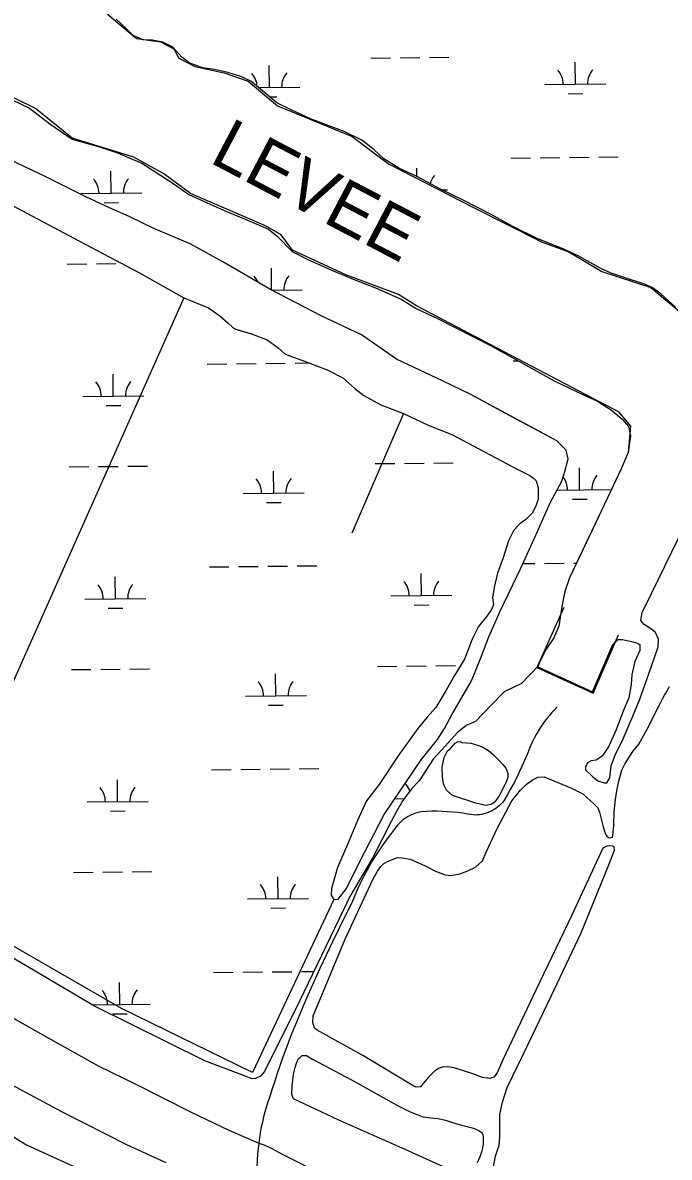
# Model space of a CAD drawing. Extents: x 3734862 to 3772949, y 391520 to 417239.
# Drawn here: x 3766777 to 3767838, y 398891 to 400752 of the extents above; entities that cross this region are included whole.
import ezdxf

# ---------------------------------------------------------------- set-up
doc = ezdxf.new("R2010")
doc.units = 0
for name, color, linetype in [('V-LEVE-TOET', 7, 'Continuous'), ('V-RIVR-IDEN', 7, 'Continuous'), ('V-ROAD-CNTR', 7, 'Continuous'), ('V-RRAP-FSHR', 7, 'Continuous'), ('V-TOPO-SHOR', 7, 'Continuous'), ('V-WETL-SWMP', 7, 'Continuous')]:
    doc.layers.add(name, color=color, linetype=linetype)

msp = doc.modelspace()

# ---------------------------------------------------------------- linework, layer by layer
at = {"layer": 'V-LEVE-TOET'}
for points in [[(3766000.7, 399623.6), (3766051.8, 399583.7), (3766152.7, 399513.4), (3766206.1, 399474.7), (3766298, 399402.4), (3766368.4, 399353.5), (3766423.4, 399316.3), (3766476.1, 399284.7), (3766539.4, 399247.6), (3766612.2, 399205), (3766714.3, 399145.7), (3766810.5, 399092), (3766901.1, 399040.7), (3766963.2, 399010.7), (3767052.6, 398965.3), (3767115.9, 398935.3), (3767147.6, 398921.9), (3767164.7, 398914.1), (3767174.6, 398910.9), (3767185.3, 398905.8), (3767205.5, 398894.7), (3767269.2, 398862.4)], [(3765933.4, 399554.7), (3765986.5, 399511.2), (3766080.7, 399441.7), (3766204.5, 399354.8), (3766290, 399298.3), (3766366.4, 399244.6), (3766432.5, 399199.2), (3766491.1, 399164.4), (3766570.6, 399118.6), (3766618.1, 399090.6), (3766684.6, 399052.3), (3766758.6, 399010.5), (3766842.5, 398965.4), (3766947.7, 398911.8), (3767012.6, 398882.2)]]:
    msp.add_lwpolyline(points, dxfattribs=at)
at = {"layer": 'V-ROAD-CNTR'}
for points in [[(3765561.3, 399764.9), (3765755.5, 399602.6), (3766144.5, 399300.8), (3766783.9, 398911.4), (3767702.3, 398491.7), (3768862.8, 397971.9), (3769048, 397895.2), (3769757.8, 397573.5), (3770042.5, 397441.9), (3770082, 397419.9), (3770108.8, 397401), (3770359.7, 397267.3)], [(3767654.6, 399629.5), (3767650.1, 399625), (3767645.7, 399620.4), (3767641.5, 399615.6), (3767637.5, 399610.7), (3767633.6, 399605.6), (3767629.9, 399600.4), (3767626.3, 399595.1), (3767623, 399589.7), (3767619.8, 399584.2), (3767616.8, 399578.6), (3767614, 399572.9), (3767611.3, 399567.1), (3767608.9, 399561.2), (3767605, 399551.3), (3767600.8, 399541.6), (3767596.5, 399531.9), (3767592, 399522.3), (3767587.4, 399512.8), (3767582.5, 399503.3), (3767577.4, 399494), (3767572.2, 399484.8), (3767566.8, 399475.6), (3767564.5, 399472.8), (3767562.1, 399470.2), (3767559.5, 399467.7), (3767556.7, 399465.4), (3767553.8, 399463.2), (3767550.8, 399461.2), (3767547.7, 399459.4), (3767544.4, 399457.8), (3767541.1, 399456.4), (3767537.7, 399455.2), (3767534.2, 399454.2), (3767530.7, 399453.4), (3767527.2, 399452.8), (3767523.6, 399452.5), (3767520, 399452.3), (3767516.3, 399452.4), (3767507.9, 399453.9), (3767499.5, 399455.2), (3767491, 399456.3), (3767482.6, 399457.1), (3767474, 399457.7), (3767465.5, 399458.2), (3767457, 399458.4), (3767448.5, 399458.4), (3767439.9, 399458.1), (3767431.4, 399457.7), (3767427.7, 399456.9), (3767424.1, 399455.9), (3767420.5, 399454.7), (3767416.9, 399453.3), (3767413.5, 399451.8), (3767410.1, 399450), (3767406.9, 399448.1), (3767403.8, 399445.9), (3767400.8, 399443.6), (3767397.9, 399441.2), (3767395.1, 399438.6), (3767392.5, 399435.8), (3767390.1, 399432.9), (3767387.8, 399429.9), (3767385.7, 399426.8), (3767379.7, 399419), (3767373.9, 399411.2), (3767368.2, 399403.2), (3767362.7, 399395.1), (3767357.4, 399386.9), (3767352.2, 399378.6), (3767347.2, 399370.2), (3767342.5, 399361.6), (3767337.8, 399353), (3767333.4, 399344.3), (3767329.1, 399335.5), (3767325.1, 399326.6), (3767321.2, 399317.6), (3767317.5, 399308.5), (3767306.7, 399287.1), (3767296, 399265.6), (3767285.5, 399244), (3767275.2, 399222.3), (3767265.1, 399200.6), (3767255.1, 399178.7), (3767245.4, 399156.8), (3767235.9, 399134.8), (3767226.5, 399112.6), (3767217.4, 399090.5), (3767212.8, 399078.1), (3767208.3, 399065.7), (3767203.8, 399053.2), (3767199.4, 399040.8), (3767195.1, 399028.3), (3767190.9, 399015.8)], [(3767190.9, 399015.8), (3767186.7, 399003.3), (3767182.7, 398990.7), (3767178.6, 398978.2), (3767174.7, 398965.7), (3767172.6, 398957.2), (3767170.7, 398948.7), (3767168.9, 398940.1), (3767167.3, 398931.5), (3767165.9, 398922.8), (3767164.7, 398914.1), (3767163.7, 398905.3), (3767162.9, 398896.6), (3767161.5, 398875.2)]]:
    msp.add_lwpolyline(points, dxfattribs=at)
at = {"layer": 'V-RRAP-FSHR'}
msp.add_lwpolyline([(3767665.1, 399792.5), (3767620.9, 399694.1), (3767713.5, 399652.4), (3767754.8, 399747.7)], dxfattribs=at)
at = {"layer": 'V-TOPO-SHOR'}
for p, q in [((3766916.2, 400766.5), (3766964.1, 400725.8)), ((3766798.5, 400611.3), (3766538.1, 400737.3)), ((3766964.1, 400725.8), (3767003.7, 400720.6)), ((3767003.7, 400720.6), (3767025.6, 400709.2)), ((3767025.6, 400709.2), (3767033.9, 400693.6)), ((3767033.9, 400693.6), (3767059.9, 400680)), ((3767059.9, 400680), (3767107.9, 400669.6)), ((3767107.9, 400669.6), (3767147.4, 400656.1)), ((3767147.4, 400656.1), (3767195.4, 400615.4)), ((3766858.9, 400562.3), (3766798.5, 400611.3)), ((3767195.4, 400615.4), (3767318.3, 400565.4)), ((3766959.9, 400531.1), (3766858.9, 400562.3)), ((3767318.3, 400565.4), (3767377.7, 400520.6)), ((3767008.9, 400504), (3766959.9, 400531.1)), ((3767377.7, 400520.6), (3767517.2, 400448.8)), ((3767052.7, 400471.7), (3767008.9, 400504)), ((3767175.6, 400418.6), (3767052.7, 400471.7)), ((3767517.2, 400448.8), (3767628.7, 400392.5)), ((3767201.6, 400404), (3767175.6, 400418.6)), ((3767220.4, 400379), (3767201.6, 400404)), ((3767628.7, 400392.5), (3767673.5, 400375.8)), ((3767307.9, 400338.3), (3767220.4, 400379)), ((3767673.5, 400375.8), (3767727.7, 400343.6)), ((3767394.3, 400306.1), (3767307.9, 400338.3)), ((3767727.7, 400343.6), (3767807.9, 400317.5)), ((3767807.9, 400317.5), (3767871.4, 400264.4)), ((3767042, 400300.7), (3766636.9, 399390.8)), ((3767423.5, 400287.3), (3767394.3, 400306.1)), ((3767755.8, 400113.3), (3767423.5, 400287.3)), ((3767402, 400110.6), (3767317.5, 399914.4)), ((3767774.5, 400090.4), (3767755.8, 400113.3)), ((3767735.8, 399401.3), (3767729.3, 399397.8))]:
    msp.add_line(p, q, dxfattribs=at)
for points in [[(3767594.2, 399856), (3767619.2, 399911.2), (3767642.7, 399964.3), (3767662.1, 399999.7), (3767666.3, 400013.3), (3767672.6, 400036.5), (3767669.2, 400050.8), (3767653.6, 400065.9), (3767588.3, 400101.2), (3767512.8, 400142), (3767467.2, 400164.1), (3767391, 400200.1), (3767333.2, 400240.1), (3767267.2, 400271.3), (3767182.8, 400314.8), (3767105.9, 400359.7), (3767052.2, 400389.4), (3766992.9, 400414.4), (3766952.1, 400433.8), (3766920.1, 400448.3), (3766881.3, 400466.4), (3766813.3, 400500.3), (3766735.7, 400537)], [(3766732.5, 400466.6), (3766870.6, 400393.4), (3766967.9, 400342.2), (3767042, 400300.7), (3767082.2, 400284.1), (3767101.2, 400271), (3767114.8, 400259.3), (3767121.6, 400252.4), (3767127.1, 400249)], [(3767288.2, 399313.9), (3767154.6, 399030.1), (3766939.4, 399134.8), (3766636.9, 399309.4), (3766264.5, 399542.1), (3765967.8, 399780.6), (3765688.5, 400001.7), (3765246.4, 400356.6), (3765194, 400414.8), (3765195.4, 400450.8)], [(3767127.1, 400249), (3767131.8, 400247.6), (3767152.9, 400241.3)], [(3767152.9, 400241.3), (3767178.8, 400231.6), (3767196.5, 400218.5), (3767207.4, 400208.8), (3767216.9, 400204.7), (3767233.9, 400199.1), (3767276.8, 400182.4), (3767302.7, 400169.3), (3767322.4, 400152.1), (3767337.3, 400140.4), (3767365.2, 400125.2), (3767402, 400110.6), (3767442.8, 400091.9), (3767481.6, 400076.6), (3767589.8, 400019.2), (3767609.6, 400008.9), (3767615.7, 400004.7), (3767619.7, 400000.6), (3767623.1, 399989), (3767623, 399970.6), (3767619.5, 399959), (3767613.3, 399947.4), (3767602.9, 399937.2), (3767593.3, 399929.8), (3767583, 399919.6), (3767574.7, 399901.9), (3767565.7, 399874), (3767556.6, 399848.8), (3767551, 399825.6), (3767548.2, 399808.5), (3767550.1, 399797.6), (3767546.7, 399789.4), (3767539.1, 399778.6), (3767525.3, 399761.6), (3767514.9, 399740.5), (3767502.4, 399707.8), (3767485.9, 399681.3), (3767472.1, 399656.8), (3767455.5, 399628.9), (3767441, 399612.6), (3767425.9, 399594.3), (3767393.5, 399549.4), (3767362.5, 399502.5), (3767341.8, 399475.3), (3767326.6, 399443.3), (3767310.6, 399403.8), (3767294, 399366.4), (3767284.2, 399331.6), (3767283.4, 399320.7), (3767288.2, 399313.9), (3767295, 399314.5), (3767308.8, 399331.5), (3767332.3, 399379.1), (3767370.3, 399453.3), (3767397.9, 399493.4), (3767431, 399543), (3767457.9, 399576.3), (3767469.6, 399594), (3767482, 399617.8), (3767503.4, 399654.5), (3767513.8, 399672.2), (3767529.1, 399710.3), (3767542.3, 399744.4), (3767561, 399786.6), (3767594.2, 399856)], [(3767774.5, 400090.4), (3767770.9, 400046.7), (3767759.2, 400020.2), (3767741.8, 399982.7), (3767712.8, 399921.5), (3767674.7, 399841.2), (3767667, 399818.7), (3767662.1, 399794.1), (3767657.1, 399762.1), (3767648.8, 399743), (3767635, 399722.6), (3767627.4, 399707), (3767625.3, 399702.2), (3767622.5, 399695.4), (3767712.4, 399654.5), (3767745.7, 399732.1), (3767754.6, 399740.3)], [(3767791.7, 399771.4), (3767793.8, 399784.4), (3767809, 399815.7), (3767853.3, 399906.2), (3767874.8, 399955.2), (3767881.8, 399974.3), (3767889.4, 399987.9), (3767900.4, 400001.5), (3767910.7, 400009.6), (3767930.8, 400016.5)], [(3767754.6, 399740.3), (3767761.4, 399740.2), (3767776.4, 399736.7), (3767784.6, 399734.6), (3767790, 399731.8), (3767790, 399722.3), (3767781.7, 399703.9), (3767776.7, 399682.1), (3767776, 399666.4), (3767771.7, 399644.6), (3767762.7, 399622.8), (3767750.9, 399592.1), (3767738.4, 399564.2), (3767728.1, 399548.6), (3767718.5, 399542.5), (3767710.3, 399541.2), (3767704.1, 399537.8), (3767700.6, 399531), (3767700.6, 399526.2), (3767712.1, 399515.2), (3767721, 399508.3), (3767731.2, 399504.9), (3767736, 399504.8), (3767740.8, 399513), (3767743, 399532.8), (3767749.9, 399551.9), (3767761, 399573.6), (3767778.3, 399614.5), (3767790.1, 399642.4), (3767801.3, 399674.4), (3767813.1, 399707.1), (3767820.1, 399728.2), (3767820.8, 399740.5), (3767815.4, 399751.5), (3767808, 399757.7), (3767797.1, 399764.6), (3767791.7, 399771.4)], [(3767822.3, 399633), (3767827.5, 399643.9), (3767830.6, 399648.9), (3767832.6, 399652.1), (3767834.6, 399655.9), (3767836.5, 399659.4), (3767838.5, 399662.9)], [(3767766, 399536.8), (3767778.5, 399556.4), (3767788.5, 399568.3), (3767802.2, 399593.2), (3767822.3, 399633)], [(3767482.8, 399484.2), (3767472.7, 399493.1), (3767468.5, 399502), (3767466.1, 399514.5), (3767465.5, 399530.5), (3767469, 399546.6), (3767474.4, 399557.3), (3767479.1, 399561.4), (3767486.8, 399570.3), (3767492.2, 399572.7), (3767496.3, 399572.1), (3767498.7, 399571.5)], [(3767498.7, 399571.5), (3767513, 399570.4), (3767518.3, 399568.6), (3767525.4, 399566.2), (3767532.6, 399563.3), (3767541.5, 399557.9), (3767550.4, 399550.2), (3767559.9, 399541.3), (3767565.3, 399535.4), (3767570, 399529.4), (3767571.8, 399525.3), (3767573.6, 399520.5), (3767573.6, 399514), (3767570.1, 399505.1), (3767558.8, 399482.5), (3767551.7, 399473.6), (3767546.3, 399469.4), (3767537.4, 399467.7), (3767520.8, 399471.8), (3767482.8, 399484.2)], [(3767550.3, 399022.2), (3767543.8, 399019.9), (3767531.9, 399021.6), (3767515.9, 399027.5), (3767485.6, 399037.6), (3767474.3, 399039.4), (3767466, 399038.8), (3767460.6, 399037), (3767452.9, 399032.2), (3767442.8, 399021.5), (3767430.4, 399006.7), (3767423.2, 399006.1), (3767419.1, 399007.3), (3767335.3, 399057.7), (3767260.4, 399099.2), (3767256.3, 399102.7), (3767253.3, 399112.2), (3767253.9, 399122.9), (3767259.8, 399137.2), (3767306, 399247.7), (3767352.2, 399346.3), (3767359.4, 399360), (3767365.3, 399367.7), (3767370, 399372.5), (3767377.2, 399376.6), (3767392.6, 399382.6), (3767400.3, 399382), (3767413.4, 399379.6), (3767436.6, 399369.6), (3767455, 399360.1), (3767470.4, 399354.1), (3767479.9, 399353), (3767494.8, 399356), (3767507.8, 399360.7), (3767520.3, 399366.7), (3767531.6, 399377.4), (3767538.1, 399391.6), (3767555.9, 399430.2), (3767580.2, 399475.4), (3767594.4, 399493.2), (3767603.3, 399502.2), (3767614, 399509.9), (3767622.9, 399514.1), (3767633, 399514.7), (3767677.6, 399496.3), (3767696.6, 399486.8), (3767714.4, 399470.8), (3767720.9, 399464.3), (3767723.9, 399457.1), (3767726.3, 399445.9), (3767729.3, 399435.2), (3767731.7, 399427.4), (3767733.5, 399420.9), (3767735.8, 399417.4), (3767738.8, 399415.6), (3767740.6, 399415), (3767745.3, 399416.2), (3767745.9, 399418), (3767747.1, 399435.2), (3767747.7, 399457.2), (3767750, 399477.9), (3767752.4, 399492.2), (3767755.3, 399507.6), (3767760.7, 399526.1), (3767766, 399536.8)], [(3767916.5, 398691.2), (3767892.1, 398699.5), (3767861.2, 398711.3), (3767737.1, 398764.1), (3767589.1, 398841.7), (3767558.8, 398856.5), (3767552.3, 398863.1), (3767549.3, 398872.6), (3767553.4, 398892.8), (3767559.3, 398910.6), (3767560.5, 398923.1), (3767560.5, 398942.7), (3767560.5, 398961.1), (3767564.6, 398981.3), (3767572.3, 399005.6), (3767600.2, 399062.7), (3767644.6, 399155.4), (3767693.8, 399259.3), (3767740, 399373.4), (3767748.3, 399394.8), (3767747.7, 399400.1), (3767745.9, 399401.3), (3767740, 399401.9), (3767735.8, 399401.3)], [(3767729.3, 399397.8), (3767678.3, 399287.8), (3767619.1, 399164.8), (3767565.1, 399050.8), (3767555.7, 399029.4), (3767550.3, 399022.2)], [(3767478.6, 398870.1), (3767400.2, 398905.7), (3767296.2, 398951.9), (3767221.9, 398986.9), (3767219, 398994), (3767219.5, 399007.7), (3767221.9, 399027.3), (3767224.3, 399038), (3767226.6, 399045.1), (3767230.2, 399052.8), (3767232.6, 399054.6), (3767236.1, 399057.6), (3767243.2, 399057.6), (3767250.4, 399053.4), (3767252.8, 399051.6)], [(3767252.8, 399051.6), (3767316.9, 399017.9), (3767392.4, 398975.8), (3767406.6, 398968.6), (3767413.2, 398965.7), (3767425.7, 398960.4), (3767434, 398957.4), (3767447, 398955.6), (3767458.9, 398954.4), (3767471.4, 398951.5), (3767482.7, 398947.9), (3767493.4, 398944.4), (3767505.9, 398941.4), (3767517.1, 398938.5), (3767526.1, 398934.9), (3767531.4, 398930.8), (3767532.6, 398927.8), (3767533.2, 398924.2), (3767533.2, 398921.9), (3767533.2, 398912.3), (3767530.8, 398901.1), (3767527.3, 398891.6), (3767523.1, 398882)]]:
    msp.add_lwpolyline(points, dxfattribs=at)
at = {"layer": 'V-WETL-SWMP'}
for p, q in [((3767348.8, 400693.8), (3767380.8, 400694.2)), ((3767396.8, 400694.3), (3767428.8, 400694.7)), ((3767444.8, 400694.9), (3767476.8, 400695.2)), ((3767684.2, 400651), (3767683.8, 400687)), ((3767182.3, 400645.7), (3767181.9, 400681.6)), ((3767164.4, 400645.5), (3767232.3, 400646.2)), ((3767634.2, 400650.4), (3767734.2, 400651.5)), ((3767182.8, 400630.2), (3767194.4, 400630.3)), ((3767672.3, 400635.4), (3767696.3, 400635.6)), ((3767578.6, 400529.8), (3767610.6, 400530.1)), ((3767626.6, 400530.3), (3767658.6, 400530.6)), ((3767674.6, 400530.8), (3767706.6, 400531.1)), ((3767722.6, 400531.3), (3767754.6, 400531.6)), ((3766922.7, 400472.2), (3766922.3, 400508.2)), ((3767424.3, 400499.3), (3767424.2, 400513.4)), ((3767465.4, 400477.8), (3767474.5, 400477.9)), ((3766872.7, 400471.6), (3766972.7, 400472.7)), ((3766910.9, 400456.6), (3766934.9, 400456.9)), ((3766850.5, 400356), (3766882.5, 400356.3)), ((3766898.5, 400356.5), (3766930.5, 400356.8)), ((3767185.8, 400313.3), (3767185.5, 400349.1)), ((3767186.2, 400313.1), (3767235.8, 400313.6)), ((3767080.3, 400191.9), (3767112.3, 400192.2)), ((3767128.3, 400192.4), (3767160.3, 400192.7)), ((3767176.3, 400192.9), (3767208.3, 400193.2)), ((3767224.3, 400193.4), (3767247.9, 400193.7)), ((3767582.1, 400197.2), (3767590.1, 400197.3)), ((3766926.2, 400139.5), (3766925.8, 400175.5)), ((3766876.2, 400139), (3766976.2, 400140.1)), ((3766914.4, 400124), (3766938.4, 400124.2)), ((3766854, 400023.3), (3766886, 400023.7)), ((3766902, 400023.8), (3766934, 400024.2)), ((3766950, 400024.3), (3766982, 400024.7)), ((3767189.4, 399980.4), (3767189, 400016.4)), ((3767355.9, 400028.6), (3767387.9, 400029)), ((3767403.9, 400029.1), (3767435.9, 400029.5)), ((3767451.9, 400029.6), (3767483.9, 400030)), ((3767691.2, 399985.7), (3767690.8, 400021.7)), ((3767139.4, 399979.9), (3767239.3, 399981)), ((3767654.2, 399985.3), (3767741.2, 399986.3)), ((3767177.5, 399964.9), (3767201.5, 399965.1)), ((3767679.4, 399970.2), (3767703.4, 399970.4)), ((3767598.1, 399864.7), (3767617.7, 399864.9)), ((3767633.7, 399865), (3767665.7, 399865.4)), ((3767681.7, 399865.6), (3767686.3, 399865.6)), ((3767083.8, 399859.2), (3767115.8, 399859.6)), ((3767131.8, 399859.7), (3767163.8, 399860.1)), ((3767179.8, 399860.3), (3767211.8, 399860.6)), ((3767227.8, 399860.8), (3767259.8, 399861.1)), ((3767431.6, 399812.2), (3767431.2, 399848.2)), ((3766929.7, 399806.9), (3766929.4, 399842.9)), ((3767381.6, 399811.6), (3767481.6, 399812.7)), ((3766879.7, 399806.3), (3766979.7, 399807.4)), ((3766917.9, 399791.3), (3766941.9, 399791.6)), ((3767419.8, 399796.6), (3767443.8, 399796.9)), ((3767359.4, 399696), (3767391.4, 399696.3)), ((3767407.4, 399696.5), (3767439.4, 399696.8)), ((3767455.4, 399697), (3767487.4, 399697.3)), ((3766857.5, 399690.7), (3766889.5, 399691)), ((3766905.5, 399691.2), (3766937.5, 399691.5)), ((3766953.5, 399691.7), (3766985.5, 399692)), ((3767192.9, 399647.8), (3767192.5, 399683.8)), ((3767142.9, 399647.2), (3767242.9, 399648.3)), ((3767181, 399632.2), (3767205, 399632.5)), ((3766933.2, 399474.2), (3766932.9, 399510.2)), ((3767087.3, 399526.6), (3767119.3, 399526.9)), ((3767135.3, 399527.1), (3767167.3, 399527.4)), ((3767183.3, 399527.6), (3767215.3, 399527.9)), ((3767231.3, 399528.1), (3767263.3, 399528.4)), ((3766883.3, 399473.7), (3766983.2, 399474.7)), ((3767388, 399479), (3767403.3, 399479.2)), ((3766921.4, 399458.7), (3766945.4, 399458.9)), ((3766861.1, 399358), (3766893.1, 399358.3)), ((3766909.1, 399358.5), (3766941.1, 399358.9)), ((3766957.1, 399359), (3766989.1, 399359.4)), ((3767196.4, 399315.1), (3767196, 399351.1)), ((3767146.4, 399314.6), (3767246.4, 399315.6)), ((3767184.5, 399299.6), (3767208.5, 399299.8)), ((3767090.8, 399193.9), (3767122.8, 399194.3)), ((3767138.8, 399194.4), (3767170.8, 399194.8)), ((3767186.8, 399194.9), (3767218.8, 399195.3)), ((3767234.8, 399195.5), (3767255.3, 399195.7)), ((3766936.8, 399141.6), (3766936.4, 399177.6)), ((3766891, 399141.1), (3766986.8, 399142.1)), ((3766924.9, 399126), (3766948.9, 399126.3))]:
    msp.add_line(p, q, dxfattribs=at)
for points in [[(3767848.3, 400285.2), (3767825.2, 400306.5), (3767811.6, 400316.2), (3767799.4, 400322.4), (3767761.2, 400334.9), (3767742.8, 400341.2), (3767727.2, 400348.1), (3767689.8, 400368.9), (3767666.6, 400379.9), (3767621.7, 400398), (3767581.5, 400417.4), (3767546.2, 400437.4), (3767499.9, 400460.9), (3767463.1, 400478.9), (3767425, 400499), (3767394.4, 400513.5), (3767369.9, 400528.7), (3767353.6, 400543.8), (3767333.9, 400559), (3767304.7, 400573.5), (3767249.5, 400594.3), (3767218.9, 400608.2), (3767194.4, 400620.6), (3767167.9, 400642.7), (3767151.6, 400655.8), (3767135.2, 400663.4), (3767114.1, 400670.3), (3767092.3, 400675.3), (3767072.5, 400678.1), (3767050.7, 400685.8), (3767038.5, 400695.4), (3767023.6, 400711.9), (3767007.2, 400720.2), (3766990.2, 400723), (3766975.2, 400723.8), (3766958.8, 400730.8), (3766947.3, 400742.4), (3766931, 400757.6)], [(3766746.5, 400631.8), (3766788.7, 400611.7), (3766822, 400586.2), (3766858.7, 400560.7), (3766903.7, 400548.1), (3766933, 400538.4), (3766973.2, 400521.7), (3767022.1, 400490), (3767050, 400470), (3767107.8, 400443.7), (3767142.6, 400429.8), (3767180.7, 400413.2), (3767195, 400401.5), (3767219.4, 400376.7), (3767245.2, 400363.6), (3767286.8, 400344.9), (3767322.2, 400330.3), (3767356.2, 400317.1), (3767398.4, 400298.4), (3767422.9, 400283.2), (3767458.3, 400266.6), (3767546.1, 400221.6), (3767607.3, 400187.8), (3767649.5, 400164.3), (3767697.8, 400141.4), (3767720.3, 400131), (3767743.4, 400116.6), (3767761.1, 400101.4), (3767771.2, 400089.7), (3767774.5, 400074), (3767770.9, 400046.7), (3767759.2, 400020.2), (3767741.9, 399982.7), (3767674.7, 399841.2), (3767667, 399818.7), (3767662.1, 399794.1), (3767657.1, 399762.1), (3767648.8, 399743), (3767635, 399722.6), (3767627.4, 399707), (3767625.3, 399702.2), (3767622.7, 399695.9), (3767595.7, 399668.2), (3767567.6, 399654.2), (3767547.1, 399633.7), (3767520.2, 399605.5), (3767504.9, 399599.1), (3767490.8, 399587.6), (3767470.5, 399565.3), (3767451.1, 399544.1), (3767428.1, 399508.2), (3767415.3, 399495.5), (3767401.2, 399476.2), (3767390.7, 399458.1), (3767382, 399441.7), (3767351.3, 399381.5), (3767314.2, 399318.8), (3767303.1, 399295.8), (3767231.9, 399146.7), (3767174.4, 399031.4)], [(3767457.9, 399576.3), (3767469.6, 399594), (3767482, 399617.8), (3767513.8, 399672.2), (3767529.1, 399710.3), (3767542.3, 399744.4), (3767561, 399786.6), (3767594.2, 399856), (3767619.2, 399911.2), (3767642.7, 399964.3), (3767662.1, 399999.7), (3767666.3, 400013.3), (3767672.6, 400036.5), (3767669.2, 400050.8), (3767653.6, 400065.9), (3767512.8, 400142), (3767467.2, 400164.1), (3767391, 400200.1), (3767333.2, 400240.1), (3767267.2, 400271.3), (3767182.8, 400314.8), (3767105.9, 400359.7), (3767052.2, 400389.4), (3766992.9, 400414.4), (3766952.1, 400433.8), (3766920.1, 400448.3), (3766881.3, 400466.4), (3766813.3, 400500.3), (3766735.7, 400537)], [(3766732.5, 400466.6), (3766870.6, 400393.4), (3766967.9, 400342.2), (3767042, 400300.7), (3767082.2, 400284.1), (3767101.2, 400271), (3767114.8, 400259.3), (3767121.6, 400252.4), (3767127.1, 400249), (3767152.9, 400241.3), (3767178.8, 400231.6), (3767196.5, 400218.5), (3767207.4, 400208.8), (3767216.9, 400204.7), (3767233.9, 400199.1), (3767276.8, 400182.4), (3767302.7, 400169.3), (3767322.4, 400152.1), (3767337.3, 400140.4), (3767365.2, 400125.2), (3767402, 400110.6), (3767442.8, 400091.9), (3767481.6, 400076.6), (3767589.8, 400019.2), (3767609.6, 400008.9), (3767615.7, 400004.7), (3767619.7, 400000.6), (3767623.1, 399989), (3767623, 399970.5), (3767619.5, 399959), (3767613.3, 399947.4), (3767602.9, 399937.2), (3767593.3, 399929.8), (3767583, 399919.6), (3767574.7, 399901.9), (3767565.7, 399874), (3767556.6, 399848.8), (3767551, 399825.6), (3767548.2, 399808.5), (3767550.1, 399797.6), (3767546.7, 399789.4), (3767539.1, 399778.6), (3767525.3, 399761.6), (3767514.9, 399740.5), (3767502.4, 399707.8), (3767485.9, 399681.3), (3767472.1, 399656.8), (3767455.5, 399628.9), (3767441, 399612.6), (3767425.9, 399594.3), (3767393.5, 399549.4), (3767362.5, 399502.5), (3767341.8, 399475.3), (3767326.6, 399443.3), (3767310.6, 399403.8), (3767294, 399366.4), (3767284.2, 399331.6), (3767283.4, 399320.7), (3767288.2, 399313.9), (3767295, 399314.5), (3767308.8, 399331.5), (3767332.3, 399379.1), (3767370.3, 399453.3), (3767397.9, 399493.4), (3767431, 399543), (3767457.9, 399576.3)], [(3767174.4, 399031.4), (3767167.8, 399024.2), (3767158.3, 399019.5), (3767152.4, 399020.1), (3767144.1, 399023.6), (3767076.4, 399049.1), (3766895.1, 399138.6), (3766688.3, 399260.8)]]:
    msp.add_lwpolyline(points, dxfattribs=at)
for centre, start, end in [((3767127, 400645.5), 2.6756, 41.377), ((3767237.5, 400646.7), 139.8334, 181.377), ((3767628.9, 400650.8), 359.8334, 41.377), ((3767739.4, 400652), 139.8334, 181.377), ((3767479.8, 400478.4), 139.8334, 164.2763), ((3766867.5, 400472.1), 359.8334, 41.377), ((3766977.9, 400473.2), 139.8334, 181.377), ((3767130.6, 400313), 22.1287, 41.377), ((3767241.1, 400314.1), 139.8334, 181.377), ((3766871, 400139.4), 359.8334, 41.377), ((3766981.5, 400140.6), 139.8334, 181.377), ((3767134.1, 399980.3), 359.8334, 41.377), ((3767244.6, 399981.5), 139.8334, 181.377), ((3767636, 399985.6), 359.8334, 36.7143), ((3767746.5, 399986.8), 139.8334, 181.377), ((3766874.5, 399806.8), 359.8334, 41.377), ((3766985, 399807.9), 139.8334, 181.377), ((3767376.4, 399812.1), 359.8334, 41.377), ((3767486.8, 399813.2), 139.8334, 181.377), ((3767137.6, 399647.7), 359.8334, 41.377), ((3767248.1, 399648.8), 139.8334, 181.377), ((3766878, 399474.1), 359.8334, 41.377), ((3766988.5, 399475.3), 139.8334, 181.377), ((3767379.9, 399479.4), 21.0326, 41.377), ((3767141.1, 399315), 359.8334, 41.377), ((3767251.6, 399316.2), 139.8334, 181.377), ((3766881.5, 399141.4), 359.8334, 41.377), ((3766992, 399142.6), 139.8334, 181.377)]:
    msp.add_arc(centre, 35.2, start, end, dxfattribs=at)

# ---------------------------------------------------------------- texts
at = {"layer": 'V-RIVR-IDEN'}
msp.add_text('LEVEE', height=83, rotation=332.2467, dxfattribs=at).set_placement((3767081.8, 400523.9))

doc.saveas('drawing.dxf')
